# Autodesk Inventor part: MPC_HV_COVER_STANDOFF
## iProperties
Shininess: 64.0
Length Units: 11269
Angle Units: 11279
Time Units: 11290
Mass Units: 11283
Length Display Precision: 3
Angle Display Precision: 2
Compacted: True
Part Number: MPC_HV_COVER_STANDOFF
Document SubType Name: Modeling
Created: 2004-08
Material: Phenolic
Designer: John Blackburn
Manufacturer: Standard
Standards Organization: Custom
Density: 0.0
Volumn: 0.0
Area: 0.0
PropertySet Name: Model Information
Control State: 0
Master: False
Checked Out: False
Author: John Blackburn
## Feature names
1. Extrusion1
